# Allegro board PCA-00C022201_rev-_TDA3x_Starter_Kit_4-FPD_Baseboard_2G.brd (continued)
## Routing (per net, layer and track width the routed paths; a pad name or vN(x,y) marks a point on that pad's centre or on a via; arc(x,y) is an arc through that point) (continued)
VDDIO_960: length 9.2
  TOP w0.381: v1(30.82,39.5) 31.05,39.28 C123.1
  TOP w0.508: C58.1 C59.1 39.89,30.92 L10.2 ; C58.1 39.72,29.97 38.72,29.97 38.55,29.8 v1(37.92,29.8) ; C58.1 C60.2
  BOTTOM w0.292: v1(37.92,29.8) U6.16
  BOTTOM w0.381: v1(33.66,37.08) R59.1 ; U7.4 v1(30.82,39.5) ; R42.1 v1(32.96,35.94)
VDDIO_HDMI_IN: length 15.5
  TOP w0.305: U44.23 48.78,43.93 v1(48.51,44.2) ; v1(69.6,61.02) 69.94,60.68 U45.8 71.47,59.46 v1(71.68,59.24) ; U44.44 v1(57.25,36.32) ; U44.34 v1(52.25,36.32)
  TOP w0.381: R283.1 v1(66.23,48.77) ; R278.2 v1(63.44,55.05) ; R286.2 v1(62.73,52.07)
  BOTTOM w0.381: R282.1 62.68,55.05 v1(63.44,55.05) ; R283.1 v1(66.23,48.77) ; v1(57.25,36.32) 57.25,37.05 C230.1 ; R287.2 v1(62.67,39.94) ; R280.1 v1(49.53,52.83) ; v1(48.51,44.2) 49.27,44.2 C232.1 ; v1(71.68,59.24) C264.1 ; R305.1 v1(69.6,61.02)
  vias: v1(50.29,37.27) v1(51.31,36.32)
VDDIO_PHY: length 5.9
  TOP w0.203: v1(89.79,28.83) 90.05,29.09 U9.41 ; U9.19 90.55,36.83 v1(90.55,37.72) ; v1(86.36,33.78) 86.52,33.63 U9.30
  TOP w0.381: R121.1 v1(88.9,25.34) ; v1(90.55,37.72) 90.42,37.85 R311.1 90.42,39.11 v1(90.42,39.12) 90.42,39.75 R125.1
  vias: v1(88.9,28.83)
VDDL: length 16
  TOP w0.508: C32.1 32.84,23.58 33.96,24.7 33.96,26.73 33.26,27.43 33.26,29.38 33.68,29.8 C31.1 C34.2 35.9,29.83 v1(35.9,30.61) ; v1(31.9,20.09) 32.26,20.45 32.65,20.45 L5.2 32.84,20.64 C33.2
  TOP w0.635: C33.2 C32.1
  BOTTOM w0.292: U6.13 v1(35.9,30.61) ; U6.44 v1(31.9,20.09)
VIN1A_CLK0: length 45.4
  TOP w0.127: J14.73 57.02,14.73 57.15,14.86 57.15,31.56 v1(56.71,32) ; R271.1 TP84.1
  BOTTOM w0.127: TP84.1 44.32,41.15 44.32,35.43 46.74,33.02 53.31,31.88 53.85,31.88 v1(56.71,32)
VIN1A_D0: length 34.3
  TOP w0.127: J14.74 v1(57.02,4.83) ; RN1.4 v1(56.68,32.89)
  INNER2 w0.127: v1(57.02,4.83) 57.02,14.1 52.13,18.99 52.13,28.35 v1(56.68,32.89)
VIN1A_D1: length 34.6
  TOP w0.127: J14.71 56.52,14.73 56.13,15.12 56.13,15.48 56.26,15.61 56.52,15.61 56.64,15.74 56.64,15.99 56.52,16.12 56.26,16.12 56.13,16.24 56.13,16.5 56.26,16.62 56.52,16.62 56.64,16.75 56.64,17.01 56.52,17.13 56.26,17.13 56.13,17.26 56.13,17.51 56.26,17.64 56.52,17.64 56.64,17.77 56.64,18.02 56.52,18.15 56.26,18.15 56.13,18.28 56.13,18.53 56.26,18.66 56.52,18.66 56.64,18.78 56.64,19.04 56.52,19.16 56.26,19.16 56.13,19.29 56.13,19.55 56.26,19.67 56.52,19.67 56.64,19.8 56.64,20.05 56.52,20.18 56.26,20.18 56.13,20.31 56.13,20.56 56.26,20.69 56.52,20.69 56.64,20.82 56.64,21.07 56.52,21.2 56.26,21.2 56.13,21.32 56.13,22.45 56.26,22.58 56.52,22.58 56.64,22.71 56.64,22.96 56.52,23.09 56.26,23.09 56.13,23.21 56.13,23.47 56.26,23.59 56.52,23.59 56.64,23.72 56.64,23.98 56.52,24.1 56.26,24.1 56.13,24.23 56.13,25.62 56.26,25.75 56.52,25.75 56.64,25.87 56.64,26.13 56.52,26.26 56.26,26.26 56.13,26.38 56.13,26.64 56.26,26.76 56.52,26.76 56.64,26.89 56.64,27.14 56.52,27.27 56.26,27.27 56.13,27.4 56.13,27.65 56.26,27.78 56.52,27.78 56.64,27.91 56.64,28.16 56.52,28.29 56.26,28.29 56.13,28.41 56.13,28.67 56.26,28.8 56.52,28.8 56.64,28.92 56.64,29.18 56.52,29.3 56.26,29.3 56.13,29.43 56.13,29.68 56.26,29.81 56.52,29.81 56.64,29.94 56.64,30.19 56.52,30.32 56.26,30.32 56.13,30.45 56.13,30.7 56.26,30.83 56.52,30.83 56.64,30.95 56.64,31.21 56.52,31.34 56.26,31.34 56.13,31.46 RN1.3
VIN1A_D2: length 34.2
  TOP w0.127: RN1.2 55.63,32.52 55.12,32 55.12,31.46 55.24,31.34 55.5,31.34 55.63,31.21 55.63,30.95 55.5,30.83 55.24,30.83 55.12,30.7 55.12,30.45 55.24,30.32 55.5,30.32 55.63,30.19 55.63,29.94 55.5,29.81 55.24,29.81 55.12,29.68 55.12,29.43 55.24,29.3 55.5,29.3 55.63,29.18 55.63,28.92 55.5,28.8 55.24,28.8 55.12,28.67 55.12,28.41 55.24,28.29 55.5,28.29 55.63,28.16 55.63,27.91 55.5,27.78 55.24,27.78 55.12,27.65 55.12,27.4 55.24,27.27 55.5,27.27 55.63,27.14 55.63,26.89 55.5,26.76 55.24,26.76 55.12,26.64 55.12,26.38 55.24,26.26 55.5,26.26 55.63,26.13 55.63,25.87 55.5,25.75 55.24,25.75 55.12,25.62 55.12,24.21 55.24,24.08 55.5,24.08 55.63,23.96 55.63,23.7 55.5,23.58 55.24,23.58 55.12,23.45 55.12,23.19 55.24,23.07 55.5,23.07 55.63,22.94 55.63,22.69 55.5,22.56 55.24,22.56 55.12,22.43 55.12,21.32 55.24,21.2 55.5,21.2 55.63,21.07 55.63,20.81 55.5,20.69 55.24,20.69 55.12,20.56 55.12,20.31 55.24,20.18 55.5,20.18 55.63,20.05 55.63,19.8 55.5,19.67 55.24,19.67 55.12,19.54 55.12,19.29 55.24,19.16 55.5,19.16 55.63,19.04 55.63,18.78 55.5,18.66 55.24,18.66 55.12,18.53 55.12,18.27 55.24,18.15 55.5,18.15 55.63,18.02 55.63,17.77 55.5,17.64 55.24,17.64 55.12,17.51 55.12,17.26 55.24,17.13 55.5,17.13 55.63,17 55.63,16.75 55.5,16.62 55.24,16.62 55.12,16.5 55.12,15.37 56.02,14.47 J14.69
VIN1A_D3: length 34.4
  TOP w0.127: RN1.1 v1(55.08,32.89) ; J14.72 v1(56.52,5.59)
  INNER2 w0.127: v1(55.08,32.89) 55.08,32.22 51.05,28.19 51.05,19.3 56.52,13.84 v1(56.52,5.59)
VIN1A_D4: length 34.7
  TOP w0.127: J14.70 v1(56.02,4.83) ; RN2.4 v1(54.14,32.89)
  INNER2 w0.127: v1(54.14,32.89) 54.14,32.17 49.91,27.94 49.91,19.68 56.02,13.58 v1(56.02,4.83)
VIN1A_D5: length 34.6
  TOP w0.127: J14.68 v1(55.52,5.59) ; RN2.3 v1(53.59,32.45)
  INNER2 w0.127: v1(53.59,32.45) 49.47,28.33 49.47,19.37 55.52,13.32 v1(55.52,5.59)
VIN1A_D6: length 40
  TOP w0.127: J14.67 55.52,14.21 54.17,15.56 54.17,16.46 54.29,16.59 54.48,16.59 54.61,16.71 54.61,16.97 54.48,17.09 53.91,17.09 53.78,17.22 53.78,17.47 53.91,17.6 54.48,17.6 54.61,17.73 54.61,17.98 54.48,18.11 53.91,18.11 53.78,18.24 53.78,18.49 53.91,18.62 54.48,18.62 54.61,18.74 54.61,19 54.48,19.13 53.91,19.13 53.78,19.25 53.78,19.51 53.91,19.63 54.48,19.63 54.61,19.76 54.61,20.01 54.48,20.14 53.91,20.14 53.78,20.27 53.78,20.52 53.91,20.65 54.48,20.65 54.61,20.78 54.61,21.03 54.48,21.16 54.29,21.16 54.17,21.28 54.17,22.42 54.29,22.55 54.48,22.55 54.61,22.67 54.61,22.93 54.48,23.05 53.91,23.05 53.78,23.18 53.78,23.44 53.91,23.56 54.48,23.56 54.61,23.69 54.61,23.94 54.48,24.07 54.29,24.07 54.17,24.2 54.17,25.59 54.29,25.71 54.48,25.71 54.61,25.84 54.61,26.09 54.48,26.22 53.91,26.22 53.78,26.35 53.78,26.6 53.91,26.73 54.48,26.73 54.61,26.86 54.61,27.11 54.48,27.24 53.91,27.24 53.78,27.36 53.78,27.62 53.91,27.74 54.48,27.74 54.61,27.87 54.61,28.13 54.48,28.25 53.91,28.25 53.78,28.38 53.78,28.63 53.91,28.76 54.48,28.76 54.61,28.89 54.61,29.14 54.48,29.27 53.91,29.27 53.78,29.4 53.78,29.65 53.91,29.78 54.48,29.78 54.61,29.9 54.61,30.16 54.48,30.28 54.29,30.28 54.17,30.41 54.17,30.92 54.01,31.08 54.01,31.26 54.21,31.46 54.21,31.64 54.03,31.82 53.85,31.82 53.65,31.62 53.47,31.62 53.09,32 RN2.2
VIN1A_D7: length 35
  TOP w0.127: J14.65 55.02,13.94 53.21,15.75 53.21,16.97 53.09,17.09 52.7,17.09 52.58,17.22 52.58,17.48 52.7,17.6 53.09,17.6 53.21,17.73 53.21,17.98 53.09,18.11 52.7,18.11 52.58,18.24 52.58,18.49 52.7,18.62 53.09,18.62 53.21,18.75 53.21,19 53.09,19.13 52.7,19.13 52.58,19.25 52.58,19.51 52.7,19.63 53.09,19.63 53.21,19.76 53.21,20.02 53.09,20.14 52.7,20.14 52.58,20.27 52.58,20.52 52.7,20.65 53.09,20.65 53.21,20.78 53.21,22.69 53.09,22.81 52.7,22.81 52.58,22.94 52.58,23.2 52.7,23.32 53.09,23.32 53.21,23.45 53.21,23.7 53.09,23.83 52.7,23.83 52.58,23.96 52.58,24.21 52.7,24.34 53.09,24.34 53.21,24.47 53.21,26.1 53.09,26.23 52.7,26.23 52.58,26.35 52.58,26.61 52.7,26.73 53.09,26.73 53.21,26.86 53.21,27.11 53.09,27.24 52.7,27.24 52.58,27.37 52.58,27.62 52.7,27.75 53.09,27.75 53.21,27.88 53.21,28.13 53.09,28.26 52.7,28.26 52.58,28.38 52.58,28.64 52.7,28.77 53.09,28.77 53.21,28.89 53.21,29.15 53.09,29.27 52.7,29.27 52.58,29.4 52.58,29.65 52.7,29.78 53.09,29.78 53.21,29.91 53.21,31.11 52.54,31.79 RN2.1
VIN1A_D8: length 38.2
  TOP w0.127: RN3.4 v1(46.52,37.72) ; J14.66 v1(55.02,4.83)
  INNER2 w0.127: v1(55.02,4.83) 55.02,13.06 49.02,19.05 49.02,33.15 46.52,35.65 v1(46.52,37.72)
VIN1A_D9: length 33.2
  TOP w0.127: J14.63 54.52,13.68 52.07,16.13 52.07,29.59 45.85,35.81 45.85,38.61 46.11,38.87 RN3.3
VIN1A_D10: length 34
  TOP w0.127: RN3.2 45.84,39.37 45.34,38.86 45.34,35.56 51.05,29.84 51.05,16.38 54.02,13.42 J14.61
VIN1A_D11: length 39.5
  TOP w0.127: RN3.1 45.63,39.92 44.83,39.12 44.83,35.31 49.78,30.35 49.78,16.89 53.34,13.34 53.34,10.54 52.32,9.53 49.53,9.53 49.24,9.82 J14.59
VIN1A_D12: length 41.7
  TOP w0.127: RN4.4 45.81,40.86 44.32,39.37 44.32,35.05 49.28,30.1 49.28,16.64 52.96,12.95 52.96,10.79 52.07,9.91 49.91,9.91 48.9,10.92 48.26,10.92 48.01,10.68 J14.57
VIN1A_D13: length 42.6
  TOP w0.127: RN4.3 45.41,41.41 v1(45.15,41.15) ; J14.62 v1(54.02,4.83)
  INNER2 w0.127: v1(45.15,41.15) 45.15,35.5 48.13,32.51 48.13,18.41 54.02,12.53 v1(54.02,4.83)
VIN1A_D14: length 42.6
  TOP w0.127: J14.64 v1(54.52,5.59) ; RN4.2 v1(45.78,41.91)
  INNER2 w0.127: v1(45.78,41.91) 45.78,35.62 48.58,32.83 48.58,18.73 54.52,12.79 v1(54.52,5.59)
VIN1A_D15: length 43.8
  TOP w0.127: RN4.1 45.5,42.46 43.81,40.77 43.81,34.8 48.77,29.84 48.77,16.38 52.58,12.57 52.58,11.05 51.82,10.29 50.29,10.29 49.21,11.37 48.07,11.37 47.51,10.81 J14.55
VIN1A_DE0: length 34.7
  TOP w0.127: J14.75 57.52,14.46 58.17,15.11 58.17,22.46 58.29,22.59 58.8,22.59 58.93,22.72 58.93,22.97 58.8,23.1 58.29,23.1 58.17,23.22 58.17,23.48 58.29,23.61 58.8,23.61 58.93,23.73 58.93,23.99 58.8,24.11 58.29,24.11 58.17,24.24 58.17,25.7 58.29,25.82 58.8,25.82 58.93,25.95 58.93,26.2 58.8,26.33 58.29,26.33 58.17,26.46 58.17,26.71 58.29,26.84 58.8,26.84 58.93,26.97 58.93,27.22 58.8,27.35 58.29,27.35 58.17,27.47 58.17,27.73 58.29,27.86 58.8,27.86 58.93,27.98 58.93,28.24 58.8,28.36 58.29,28.36 58.17,28.49 58.17,28.74 58.29,28.87 58.8,28.87 58.93,29 58.93,29.25 58.8,29.38 58.29,29.38 58.17,29.51 58.17,29.76 58.29,29.89 58.8,29.89 58.93,30.01 58.93,30.27 58.8,30.4 58.29,30.4 58.17,30.52 58.17,30.78 58.29,30.9 58.8,30.9 58.93,31.03 58.93,31.28 58.8,31.41 58.29,31.41 58.17,31.54 58.17,32.19 TP86.1 57.78,33.08 R274.1
VIN1A_HSYNC0: length 34
  TOP w0.127: J14.78 v1(58.02,4.83) ; TP85.1 R272.1
  INNER2 w0.127: v1(58.02,4.83) 58.02,14.63 54.17,18.48 54.17,27.5 58.93,32.26 TP85.1
VIN1A_VSYNC0: length 37.3
  TOP w0.127: J14.76 v1(57.52,5.59) ; TP87.1 60.07,33.08 R273.1
  INNER2 w0.127: TP87.1 59.63,33.53 58.61,33.53 58.23,33.15 58.23,32.32 53.15,27.24 53.15,18.73 57.52,14.37 v1(57.52,5.59)
ADC_IN2: length 77.7
  TOP w0.152: J14.20 v1(38.51,5.59)
  TOP w0.381: D21.C v1(24.19,57.59)
  INNER1 w0.152: v1(24.19,57.59) 28.64,57.59 30.35,55.88 33.15,55.88 36.7,52.32 36.7,47.62 38.61,45.72 38.61,44.07 37.97,43.43 37.97,34.54 41.02,31.5 41.02,28.45 41.91,27.56 41.91,26.92 34.29,19.3 34.29,13.46 36.32,11.43 36.32,9.78 37.4,8.7 37.4,7.94 38.51,6.83 v1(38.51,5.59)
  BOTTOM w0.254: v1(24.19,57.59) 22.61,57.59 22.29,57.91 R231.1 R26.1
ADC_IN4: length 70.3
  TOP w0.152: v1(37.97,8.38) 37.51,8.84 J14.15 ; v1(33.27,62.1) 28.7,62.1 28.26,62.55 R251.2
  INNER1 w0.152: v1(37.97,8.38) 37.97,10.79 37.53,11.24 37.53,11.75 37.34,11.94 37.34,12.83 37.97,13.46 37.97,18.41 39.37,19.81 39.37,22.61 43.81,27.05 43.81,30.73 39.24,35.31 39.24,42.93 39.88,43.56 39.88,46.35 38.48,47.75 38.48,56.9 v1(33.27,62.1)
ADC_IN5: length 89.5
  TOP w0.152: v1(37.01,10.92) J14.13
  TOP w0.254: R252.2 v1(6.67,60.26)
  INNER1 w0.152: v1(37.01,10.92) 37.01,11.5 36.7,11.81 36.7,18.03 38.73,20.07 38.73,22.86 42.55,26.67 42.55,30.99 38.61,34.92 38.61,43.18 39.24,43.81 39.24,46.1 37.97,47.37 37.97,56.64 32.99,61.63 23.02,61.63 22.23,60.83 16.89,60.83 15.24,62.48 15.24,63.12 14.22,64.14 11.68,64.14 7.81,60.26 v1(6.67,60.26)
ADV7611_RSTN: length 83.9
  TOP w0.127: v1(63.75,42.67) 63.5,42.93 U44.56 ; U22.10 27.06,8.63 24.89,10.79 24.89,13.08 18.8,19.18 18.8,34.67 24.19,40.07 32.51,40.07 32.96,39.62 42.8,39.62 43.18,39.24 v1(43.18,38.61)
  INNER1 w0.127: v1(43.18,38.61) 43.69,38.61 46.35,41.27 51.69,41.27 52.07,41.66 57.02,41.66 58.29,42.93 61.09,42.93 61.34,42.67 v1(63.75,42.67)
  BOTTOM w0.127: v1(63.75,42.67) 63.75,41.91 R290.1
ADV7611_SCL: length 26.7
  TOP w0.127: v1(63.31,41.02) 62.9,41.43 U44.53 ; v1(42.99,36.39) R291.2 R288.1
  INNER1 w0.127: v1(42.99,36.39) 46.1,39.5 59.82,39.5 61.75,41.43 62.9,41.43 v1(63.31,41.02)
ADV7611_SDA: length 24.4
  TOP w0.127: R289.1 R292.2 v1(42.99,37.53) ; v1(62.48,41.93) U44.54
  INNER1 w0.127: v1(42.99,37.53) 43.37,37.53 46.42,40.58 57.85,40.58 59.2,41.93 v1(62.48,41.93)
BB_3V3_PG: length 47
  TOP w0.152: TP56.1 76.02,2.62 J14.130
  TOP w0.254: U1.10 106.95,15.93 v1(106.95,15.56)
  INNER2 w0.152: TP28.1 99.69,17.14 97.03,14.48 97.03,9.02 v1(91.06,3.05)
  BOTTOM w0.152: TP56.1 77.3,1.33 86.8,1.33 88.52,3.05 v1(91.06,3.05)
  BOTTOM w0.203: v1(106.95,15.56) 103.71,18.8 TP28.1 98.43,18.8 R8.2
BOARD_ID0: length 13.1
  TOP w0.127: R185.2 R186.1 11.49,9.08 12.83,10.41 20.7,10.41 21.19,9.93 U22.13
BOARD_ID1: length 10.3
  TOP w0.127: U22.14 21.08,9.28 20.45,9.91 14.99,9.91 14.16,9.08 R187.1 R188.2
BOARD_ID2: length 7.5
  TOP w0.127: R190.2 R189.1 16.83,9.08 17.14,9.4 20.19,9.4 20.97,8.63 U22.15
BOARD_ID3: length 4.2
  TOP w0.127: U22.16 20.85,7.98 20.19,8.64 R191.1 R192.2
BUF_INPUT0: length 1.1
  BOTTOM w0.152: R265.1 J28.2
BUF_INPUT1: length 1.1
  BOTTOM w0.152: R266.1 J28.4
BUF_OUT0: length 1.1
  BOTTOM w0.152: R267.1 J28.6
BUF_OUT1: length 1.1
  BOTTOM w0.152: R268.1 J28.8
CSI2_0_DX0: length 47.8
  TOP w0.127: v1(65.18,5.36) 65.03,5.51 64.57,5.51 64.44,5.38 64.44,3.72 J14.104
  BOTTOM w0.127: v1(65.18,5.36) 65.03,5.51 64.53,5.51 64.1,5.94 64.1,7.39 65.71,9 65.71,9.11 65.65,9.17 65.65,9.28 65.72,9.35 65.82,9.35 65.89,9.29 66,9.29 66.07,9.36 66.07,9.47 66.01,9.52 66.01,9.63 66.09,9.7 66.19,9.7 66.25,9.64 66.35,9.64 67.18,10.47 67.18,13.72 62.46,18.44 50.4,18.44 42.67,26.17 38.18,26.17 U6.23
CSI2_0_DX1: length 47.8
  TOP w0.127: J14.109 65.94,9.89 65.94,11.67 65.61,12 65.23,12 v1(65.08,12.15)
  BOTTOM w0.127: v1(65.08,12.15) 65.23,12 65.62,12 65.86,12.24 65.86,13.07 63.13,15.8 63.03,15.8 62.97,15.74 62.87,15.74 62.79,15.82 62.79,15.92 62.85,15.98 62.85,16.08 62.77,16.16 62.67,16.16 62.6,16.09 62.5,16.09 62.42,16.17 62.42,16.27 62.49,16.34 62.49,16.44 62.2,16.73 61.43,16.73 61.18,16.48 61.18,15.96 60.84,15.62 60.17,15.62 59.83,15.96 59.83,16.79 59.7,16.92 59.32,16.92 59.2,16.79 59.2,15.96 58.86,15.62 58.18,15.62 57.85,15.96 57.85,16.79 57.72,16.92 57.34,16.92 57.21,16.79 57.21,15.96 56.88,15.62 56.2,15.62 55.86,15.96 55.86,16.79 55.74,16.92 55.35,16.92 55.23,16.79 55.23,15.96 54.89,15.62 54.21,15.62 53.88,15.96 53.88,16.79 53.75,16.92 53.37,16.92 53.24,16.79 53.24,15.96 52.91,15.62 52.23,15.62 51.89,15.96 51.89,16.5 51.5,16.89 50.04,16.89 41.76,25.17 38.18,25.17 U6.25
CSI2_0_DX2: length 47.8
  TOP w0.127: v1(63.51,12.15) 63.67,12 64.11,12 64.44,11.67 64.44,9.89 J14.103
  BOTTOM w0.127: v1(63.51,12.15) 63.67,12 63.95,12 64.11,12.16 64.11,13.03 63.1,14.05 62.35,14.05 62.28,13.97 62.28,13.74 62.2,13.67 62.1,13.67 62.03,13.74 62.03,13.97 61.95,14.05 61.26,14.05 61.14,13.92 61.14,12.13 60.8,11.8 60.12,11.8 59.79,12.13 59.79,13.92 59.66,14.05 59.28,14.05 59.15,13.92 59.15,12.11 58.82,11.77 58.14,11.77 57.8,12.11 57.8,13.92 57.68,14.05 57.3,14.05 57.17,13.92 57.17,12.11 56.83,11.77 56.16,11.77 55.82,12.11 55.82,13.92 55.49,14.25 50.77,14.25 40.85,24.17 38.18,24.17 U6.27
CSI2_0_DX3: length 47.8
  TOP w0.127: J14.98 62.94,3.72 62.94,5.38 63.07,5.51 63.32,5.51 v1(63.47,5.36)
  BOTTOM w0.127: v1(63.47,5.36) 63.32,5.51 62.95,5.51 62.57,5.88 62.57,9.12 61.76,9.93 61.19,9.93 61.11,9.86 61.11,9.77 61.04,9.7 60.93,9.7 60.86,9.77 60.86,9.86 60.78,9.93 60.68,9.93 60.6,9.86 60.6,9.77 60.53,9.7 60.42,9.7 60.35,9.77 60.35,9.86 60.27,9.93 59.78,9.93 59.54,9.69 59.54,9.35 59.2,9.02 58.53,9.02 58.19,9.35 58.19,9.8 58.06,9.93 57.68,9.93 57.56,9.8 57.56,9.35 57.22,9.02 56.54,9.02 56.21,9.35 56.21,9.71 55.99,9.93 55.22,9.93 52.33,12.83 50.04,12.83 49.52,13.35 49.34,13.35 48.58,12.6 48.11,12.6 47.63,13.08 47.63,13.55 48.38,14.31 48.38,14.49 48.11,14.76 47.93,14.76 47.18,14 46.7,14 46.23,14.48 46.23,14.96 46.98,15.71 46.98,15.89 46.71,16.16 46.53,16.16 45.78,15.41 45.3,15.41 44.82,15.88 44.82,16.36 45.58,17.11 45.58,17.55 39.95,23.17 38.18,23.17 U6.29
CSI2_0_DX4: length 47.8
  TOP w0.127: J14.97 62.94,9.75 62.94,7.9 62.61,7.57 62.18,7.57 v1(62.03,7.42)
  BOTTOM w0.127: v1(62.03,7.42) 61.88,7.57 54.41,7.57 52.45,9.53 50.42,9.53 50.16,9.78 49.02,9.78 48.68,10.11 48.68,10.85 48.55,10.97 48.17,10.97 48.04,10.85 48.04,10.11 47.71,9.78 45.09,9.78 43.89,10.98 43.89,11.45 45.21,12.78 45.21,12.96 44.94,13.23 44.76,13.23 43.44,11.9 42.97,11.9 41.81,13.06 41.81,14.41 42.14,14.75 43.2,14.75 43.33,14.88 43.33,15.26 43.2,15.38 42.14,15.38 41.81,15.72 41.81,16.4 42.14,16.73 43.2,16.73 43.33,16.86 43.33,17.24 43.2,17.37 42.14,17.37 41.81,17.7 41.81,19.38 39.02,22.17 38.18,22.17 U6.31
CSI2_0_DY0: length 47.9
  TOP w0.127: J14.102 64.09,3.72 64.09,5.53 64.42,5.87 64.8,5.87 65.03,5.87 v1(65.18,6.02)
  BOTTOM w0.127: v1(65.18,6.02) 65.03,5.87 64.68,5.87 64.45,6.09 64.45,7.24 67.54,10.33 67.54,13.87 62.61,18.8 50.55,18.8 42.82,26.53 38.18,26.53 U6.22
CSI2_0_DY1: length 47.8
  TOP w0.127: J14.107 65.59,9.89 65.59,11.52 65.46,11.65 65.23,11.65 v1(65.08,11.49)
  BOTTOM w0.127: v1(65.08,11.49) 65.23,11.65 65.77,11.65 66.22,12.1 66.22,13.22 62.35,17.08 61.28,17.08 60.82,16.63 60.82,16.1 60.7,15.98 60.32,15.98 60.19,16.1 60.19,16.94 59.85,17.27 59.18,17.27 58.84,16.94 58.84,16.1 58.71,15.98 58.33,15.98 58.2,16.1 58.2,16.94 57.87,17.27 57.19,17.27 56.86,16.94 56.86,16.1 56.73,15.98 56.35,15.98 56.22,16.1 56.22,16.94 55.88,17.27 55.21,17.27 54.87,16.94 54.87,16.1 54.74,15.98 54.36,15.98 54.24,16.1 54.24,16.94 53.9,17.27 53.22,17.27 52.89,16.94 52.89,16.1 52.76,15.98 52.38,15.98 52.25,16.1 52.25,16.65 51.65,17.25 50.19,17.25 41.91,25.53 38.18,25.53 U6.24
CSI2_0_DY2: length 47.8
  TOP w0.127: J14.101 64.09,9.89 64.09,11.52 63.96,11.65 63.66,11.65 v1(63.51,11.49)
  BOTTOM w0.127: v1(63.51,11.49) 63.66,11.65 64.1,11.65 64.47,12.01 64.47,13.18 63.25,14.4 61.12,14.4 60.78,14.07 60.78,12.28 60.65,12.15 60.27,12.15 60.14,12.28 60.14,14.07 59.81,14.4 59.13,14.4 58.8,14.07 58.8,12.26 58.67,12.13 58.29,12.13 58.16,12.26 58.16,14.07 57.83,14.4 57.15,14.4 56.81,14.07 56.81,12.26 56.69,12.13 56.3,12.13 56.18,12.26 56.18,14.07 55.64,14.61 50.92,14.61 41,24.53 38.18,24.53 U6.26
CSI2_0_DY3: length 47.8
  TOP w0.127: J14.96 62.59,3.72 62.59,5.53 62.92,5.87 63.32,5.87 v1(63.47,6.02)
  BOTTOM w0.127: v1(63.47,6.02) 63.32,5.87 63.09,5.87 62.93,6.03 62.93,9.27 61.91,10.29 59.63,10.29 59.18,9.84 59.18,9.5 59.06,9.37 58.67,9.37 58.55,9.5 58.55,9.95 58.21,10.29 57.53,10.29 57.2,9.95 57.2,9.5 57.07,9.37 56.69,9.37 56.56,9.5 56.56,9.86 56.13,10.29 55.37,10.29 52.48,13.18 50.19,13.18 49.67,13.71 49.19,13.71 48.44,12.95 48.26,12.95 47.99,13.22 47.99,13.4 48.74,14.16 48.74,14.63 48.26,15.11 47.79,15.11 47.03,14.36 46.85,14.36 46.58,14.63 46.58,14.81 47.34,15.56 47.34,16.04 46.86,16.52 46.38,16.52 45.63,15.76 45.45,15.76 45.18,16.03 45.18,16.21 45.93,16.97 45.93,17.69 40.1,23.53 38.18,23.53 U6.28
CSI2_0_DY4: length 47.8
  TOP w0.127: J14.95 62.59,9.75 62.59,8.05 62.46,7.93 62.18,7.93 v1(62.03,8.08)
  BOTTOM w0.127: U6.30 38.18,22.53 39.16,22.53 42.16,19.53 42.16,17.85 42.29,17.72 43.35,17.72 43.69,17.39 43.69,16.71 43.35,16.38 42.29,16.38 42.16,16.25 42.16,15.87 42.29,15.74 43.35,15.74 43.69,15.4 43.69,14.73 43.35,14.39 42.29,14.39 42.16,14.27 42.16,13.21 43.11,12.26 43.29,12.26 44.62,13.58 45.09,13.58 45.57,13.1 45.57,12.63 44.25,11.31 44.25,11.13 45.24,10.13 47.56,10.13 47.69,10.26 47.69,10.99 48.02,11.33 48.7,11.33 49.04,10.99 49.04,10.26 49.16,10.13 50.31,10.13 50.57,9.88 52.6,9.88 54.55,7.93 60.25,7.93 60.33,8 60.33,8.09 60.4,8.17 60.51,8.17 60.58,8.09 60.58,8 60.65,7.93 60.76,7.93 60.83,8 60.83,8.08 60.91,8.15 61.01,8.15 61.09,8.08 61.09,8 61.16,7.93 61.88,7.93 v1(62.03,8.08)
CVDD_HDMI_IN: length 4.2
  TOP w0.305: v1(52.58,50.1) 52.75,49.93 U44.14 ; U44.2 v1(58.75,50.04)
  BOTTOM w0.457: C246.1 52.32,49.85 v1(52.58,50.1) ; v1(58.75,50.04) 58.93,49.86 C247.1
  vias: v1(49.53,49.78) v1(49.53,49.02) v1(60.45,48.51)
DCAN1_H: length 12.6
  TOP w0.127: J28.1 112.27,66.29 112.07,66.49 D9.1 108.33,66.49 107.64,67.18 106.24,67.18 105.44,66.38 R92.1 105.43,66.36 C107.1 103.63,66.36 103.5,66.23 U10.7
DCAN1_L: length 12.6
  TOP w0.127: J28.3 112.39,65.02 112.07,64.7 D8.2 108.26,64.7 107.57,64.01 106.24,64.01 105.44,64.81 R93.1 105.43,64.84 C108.1 103.63,64.84 103.5,64.96 U10.6
DCAN1_RX: length 76.3
  TOP w0.152: J14.113 v1(67.02,8.64) ; v1(99.82,62.67) 99,61.85 88.39,61.85 86.87,60.33 86.87,58.8 85.22,57.15 84.33,57.15 77.47,50.29 v1(77.47,31.75)
  INNER1 w0.152: v1(77.47,31.75) 77.47,22.73 72.14,17.4 72.14,13.76 v1(67.02,8.64)
  BOTTOM w0.152: v1(99.82,62.67) R91.1
DCAN1_STSB: length 119.5
  TOP w0.152: U22.11 v1(30.1,9.28) ; v1(75.69,29.97) 75.69,49.4 84.07,57.78 85.09,57.78 86.36,59.05 86.36,60.58 88.07,62.29 98.49,62.29 v1(100.52,64.33)
  INNER1 w0.152: v1(30.1,9.28) 30.86,8.51 30.86,7.62 34.68,3.81 47.94,3.81 49.72,5.59 51.18,5.59 53.34,7.75 56.26,7.75 62.87,14.35 67.06,14.35 75.69,22.99 v1(75.69,29.97)
  BOTTOM w0.152: v1(100.52,64.33) 102.17,65.98 R89.1
DCAN1_TX: length 75.6
  TOP w0.152: v1(78.11,32.38) 78.11,49.97 v1(83.19,55.05) ; J14.115 67.52,8.31 v1(67.03,7.82)
  INNER1 w0.152: v1(67.03,7.82) 72.64,13.44 72.64,17.27 78.11,22.73 v1(78.11,32.38)
  BOTTOM w0.152: R90.1 97.41,65.53 92.58,60.71 88.84,60.71 v1(83.19,55.05)
DCAN2_RX: length 67.3
  TOP w0.152: J14.110 v1(66.02,4.83)
  INNER2 w0.152: J27.14 41.15,50.67 41.15,46.99 44.51,43.62 44.51,34.8 46.04,33.27 46.04,19.75 53.47,12.32 53.47,4.45 53.85,4.06 65.25,4.06 v1(66.02,4.83)
DCAN2_TX: length 71.2
  TOP w0.152: J14.108 v1(65.52,2.54)
  INNER2 w0.152: v1(65.52,2.54) 64.5,3.56 53.59,3.56 52.96,4.19 52.96,12.06 45.59,19.43 45.59,33.02 43.94,34.67 43.94,43.18 38.48,48.64 38.48,53.09 J27.12
EDID_EEPROM_WP: length 112.5
  TOP w0.152: v1(70.05,57.76) 69.29,58.53 U45.7 ; SW2.4 v1(15.24,5.71)
  INNER1 w0.152: v1(37.08,46.16) 36.13,45.21 32.13,45.21 26.54,39.62 26.54,32.51 22.48,28.45 22.48,22.35 20.32,20.19 20.32,19.3 19.3,18.29 19.3,9.65 21.72,7.24 21.72,2.6 21.34,2.22 18.22,2.22 16.07,4.38 16.07,4.89 v1(15.24,5.71)
  BOTTOM w0.152: v1(37.08,46.16) 38.35,47.43 38.35,57.78 38.86,58.29 43.43,58.29 45.72,60.58 60.58,60.58 61.91,59.24 R305.2 69.6,58.22 v1(70.05,57.76)
EDID_SCL: length 7.8
  TOP w0.127: TP88.1 68.64,57.88 U45.6
  BOTTOM w0.127: U46.4 66.1,54.03 68.33,56.26 68.33,56.97 TP88.1
EDID_SDA: length 5.5
  TOP w0.127: U45.5 67.99,57.9 TP89.1
  BOTTOM w0.127: TP89.1 67.06,56.97 67.06,56.64 66.4,55.98 U46.7
EDID_SEL: length 99.7
  TOP w0.152: R307.2 v1(65.05,51.44) ; SW2.3 v1(15.24,4.45)
  INNER1 w0.152: v1(37.97,45.09) 37.47,44.58 32.51,44.58 27.18,39.24 27.18,32.26 24,29.08 24,22.99 20.95,19.94 20.95,19.05 19.94,18.03 19.94,9.91 22.23,7.62 22.23,2.41 21.65,1.84 17.84,1.84 v1(15.24,4.45)
  BOTTOM w0.152: U46.1 v1(65.05,51.44) 61.59,51.44 61.09,51.94 60.45,51.94 58.8,53.59 58.8,53.98 58.29,54.48 45.72,54.48 44.45,53.21 44.45,48.77 40.77,45.09 v1(37.97,45.09)
EMU0: length 52.2
  TOP w0.127: J14.175 v1(87.52,8.47)
  INNER2 w0.127: v1(87.52,8.47) 87.52,8.11 89.41,6.22 89.41,3.43 87.5,1.52 78.17,1.52 75.12,4.57 75.12,5.27 74.17,6.22 74.17,6.99 62.85,18.3 62.85,23.05 v1(60.95,24.96)
  BOTTOM w0.127: J13.19 59.89,24.66 60.19,24.96 v1(60.95,24.96)
EMU1: length 55.5
  TOP w0.127: v1(89.2,7.94) 87.3,7.94 87.02,8.22 J14.173
  INNER2 w0.127: v1(61.58,20.19) 62.09,19.68 62.09,17.54 73.15,6.48 73.15,4.06 74.87,2.35 74.87,1.52 75.63,0.76 88.01,0.76 90.17,2.92 90.17,6.97 v1(89.2,7.94)
  BOTTOM w0.127: J13.21 59.39,22.1 59.18,21.89 59.18,20.45 59.44,20.19 v1(61.58,20.19)
EMU_RSTN: length 38.9
  TOP w0.127: J14.172 v1(86.52,5.52) ; R108.2 63.15,30.87 v1(63.39,30.63)
  INNER2 w0.127: v1(86.52,5.52) 86.36,5.97 65.15,27.18 65.15,28.87 v1(63.39,30.63)
  BOTTOM w0.127: J13.6 v1(63.39,30.63)
ENET_CLKIN: length 2.5
  TOP w0.127: R233.2 93.32,38.33 92.56,37.56 U9.15
FPD_960_EN: length 38.6
  TOP w0.152: U22.17 23.2,7.33 v1(23.75,7.87) ; R270.1 v1(28.7,39.5)
  INNER1 w0.152: v1(28.7,39.5) 27.81,38.61 27.81,32 24.64,28.83 24.64,21.34 20.83,17.53 20.83,13.59 21.46,12.95 21.46,10.16 v1(23.75,7.87)
FPD_960_GPIO4: length 42.1
  TOP w0.152: TP22.1 29.44,4.72 U22.4
  INNER1 w0.152: v1(39.12,29.26) 36.12,29.26 34.16,27.3 34.16,24.97 30.21,21.02 26.29,21.02 23.24,17.97 23.24,13.59 23.88,12.95 23.88,10.29 TP22.1
  BOTTOM w0.152: U6.17 38.65,29.1 38.81,29.26 v1(39.12,29.26)
FPD_960_GPIO5: length 38.3
  TOP w0.152: TP24.1 29.46,5.46 29.38,5.37 U22.5
  INNER1 w0.152: TP24.1 29.46,5.46 24.38,10.54 24.38,13.21 23.8,13.79 23.8,17.83 26.54,20.57 30.53,20.57 36.7,26.75 36.7,27.5 37.81,28.6 v1(38.91,28.6)
  BOTTOM w0.152: U6.18 v1(38.91,28.6)
FPD_960_GPIO6: length 35.7
  TOP w0.152: TP23.1 29.27,6.02 U22.6
  INNER1 w0.152: v1(39.22,27.99) 38.66,27.99 38.23,27.56 38.23,25.27 32.32,19.37 29.15,19.37 24.89,15.11 24.89,10.79 28.83,6.86 TP23.1
  BOTTOM w0.152: v1(39.22,27.99) 39.11,28.1 U6.19
FPD_960_GPIO7: length 32.1
  TOP w0.152: TP25.1 29.34,7.49 29.34,6.99 29.03,6.68 U22.7
  INNER1 w0.152: v1(38.98,27.37) 38.98,25.13 32.7,18.86 29.27,18.86 26.1,15.68 26.1,12.26 TP25.1
  BOTTOM w0.152: v1(38.98,27.37) 38.75,27.6 U6.20
FPD_960_IDX: length 7.1
  BOTTOM w0.152: U6.46 30.9,19.63 32.5,18.04 C63.1 R53.1 R51.2
FPD_960_MODE: length 9
  BOTTOM w0.152: U6.45 31.41,19.83 32.44,18.8 36.88,18.8 37.21,18.47 R58.2 R61.1
FPD_960_PDB: length 9.5
  TOP w0.152: v1(29.65,36.83) 29.65,37.53 R269.1 R270.2
  BOTTOM w0.152: v1(29.65,36.83) 29.65,31.94 30.9,30.69 U6.3
FPD_960_REFCLK: length 1.2
  BOTTOM w0.127: U7.3 R45.1
FPD_960_SCL: length 8.2
  BOTTOM w0.127: R38.1 R39.1 38.73,34.67 38.35,34.29 37.97,34.29 36.7,33.02 36.7,32.26 35.41,30.96 35.41,29.8 U6.12
FPD_960_SCL2: length 15.5
  TOP w0.127: v1(34.67,35.24) R44.1 R328.2
  INNER2 w0.127: J29.1 36.45,37.02 v1(34.67,35.24)
  BOTTOM w0.127: R43.1 R44.1 v1(34.67,35.24) 34.23,34.8 34.23,33.08 33.41,32.26 U6.8
FPD_960_SDA: length 10.8
  BOTTOM w0.127: R37.1 R36.1 38.23,37.53 37.85,37.15 37.85,34.92 36.2,33.27 36.2,32.51 34.9,31.22 34.9,29.8 U6.11
FPD_960_SDA2: length 14.4
  TOP w0.127: v1(34.67,37.21) 34.67,38.03 R329.2
  BOTTOM w0.127: U6.7 32.9,32.52 33.78,33.4 33.78,36.32 v1(34.67,37.21) 34.99,37.53 R40.1 R41.1 35.43,39.88 J29.2
FPD_960_TESTEN: length 18.3
  TOP w0.152: v1(25.4,28.45) SW1.2
  TOP w0.203: v1(31.38,30.58) 32.36,30.58 33.72,31.94 R60.2
  INNER1 w0.152: v1(25.4,28.45) 29.25,28.45 v1(31.38,30.58)
  BOTTOM w0.152: v1(31.38,30.58) 31.39,30.57 31.39,29.81 U6.4
GPIO2_0: length 104
  TOP w0.152: J14.77 58.02,8.87 57.72,8.57 53.21,8.57 52.7,9.08 51.05,9.08 v1(50.48,8.51)
  INNER1 w0.152: v1(24.96,58.29) 24,58.29 18.67,52.96 18.67,9.4 20.19,7.87 20.19,6.67 v1(20.89,5.97)
  BOTTOM w0.152: v1(50.48,8.51) 45.59,8.51 44.45,7.37 39.5,7.37 37.82,5.69 37.82,4.75 37.13,4.06 34.04,4.06 31.94,6.16 23.94,6.16 23.75,5.97 v1(20.89,5.97)
  BOTTOM w0.254: R231.2 22.29,58.93 22.92,58.29 v1(24.96,58.29)
GPIO2_19: length 66.8
  TOP w0.127: R180.1 R234.1 85.41,26.03 TP40.1 ; J14.56 47.51,5.1 v1(48.01,5.59)
  BOTTOM w0.127: TP40.1 85.41,18.67 84.52,17.78 84.52,10.6 86.11,9.02 86.11,8.32 85.53,7.75 85.53,4.38 85.28,4.13 76.14,4.13 74.99,5.27 74.1,5.27 72.77,3.94 53.59,3.94 51.94,5.59 v1(48.01,5.59)
GPIO3_19: length 94.7
  TOP w0.152: U41.6 120.89,60.44 119.89,59.44 116.33,59.44 116.14,59.25 114.11,59.25 113.74,58.88 113.74,58.37 113.41,58.04 111.76,58.04 111.25,58.55 111.25,58.8 110.87,59.18 109.98,59.18 109.09,60.07 92.71,60.07 90.3,57.66 90.3,55.75 80.26,45.72 80.26,31.62 61.02,12.38 J14.89
GPIO3_20: length 98.7
  TOP w0.152: U41.4 120.89,61.74 120.01,62.61 118.11,62.61 116.71,61.21 116.71,60.71 115.7,59.69 113.67,59.69 112.59,60.77 112.59,61.34 112.2,61.72 104.58,61.72 104.08,62.23 100.33,62.23 99.5,61.4 91.76,61.4 88.77,58.42 88.77,56.52 78.74,46.48 78.74,32 59.02,12.28 J14.81
GPIO3_21: length 94.1
  TOP w0.152: J14.85 60.02,12.65 79.25,31.88 79.25,46.23 89.28,56.26 89.28,58.17 92.08,60.96 110.87,60.96 v1(113.16,58.67)
  BOTTOM w0.152: v1(113.16,58.67) R297.1 113.85,59.37 114.24,59.75 119,59.75 119.2,59.55 U42.1
GPIO3_22: length 94.3
  TOP w0.152: J14.87 60.52,12.51 79.76,31.75 79.76,45.97 89.79,56.01 89.79,57.91 92.39,60.52 110.55,60.52 112.01,59.05 v1(112.01,58.67)
  BOTTOM w0.152: R298.1 v1(112.01,58.67) 112.01,58.17 114.17,56.01 116.01,56.01 117.9,57.9 U42.3
GPIO3_23: length 108.4
  TOP w0.152: J14.83 59.52,8.84 58.23,7.56 v1(51.37,7.56)
  INNER1 w0.152: v1(20.89,4.45) 19.94,5.4 18.48,5.4 18.16,5.71 18.16,6.48 17.4,7.24 17.4,46.23 5.84,57.78 v1(5.84,59.44)
  BOTTOM w0.152: v1(51.37,7.56) 50.81,7.05 50.1,6.35 40.96,6.35 37.66,3.05 33.53,3.05 32.38,4.19 31.24,4.19 30.42,3.37 29.78,3.37 28.38,4.76 24.45,4.76 24.13,4.45 v1(20.89,4.45) ; R24.1 6.34,60.82 5.84,60.33 v1(5.84,59.44)
GPIO3_24: length 105.4
  TOP w0.152: J14.79 58.52,8.61 57.98,8.06 52.96,8.06 52.51,8.51 v1(51.37,8.51)
  INNER1 w0.152: v1(23.18,60.77) 20.13,57.72 20.13,56.07 18.03,53.98 18.03,7.43 19.43,6.03 20.07,6.03 v1(20.89,5.21)
  BOTTOM w0.152: v1(20.89,5.21) 21.25,4.85 23.77,4.85 24.26,5.33 28.7,5.33 29.27,4.76 32.58,4.76 33.78,3.56 37.47,3.56 40.77,6.86 44.83,6.86 46,8.03 50.89,8.03 v1(51.37,8.51)
  BOTTOM w0.254: v1(23.18,60.77) 22.29,60.77 22.16,60.64 R25.1
GPIO4_5: length 90.3
  TOP w0.152: J14.161 v1(84.02,10.92)
  INNER1 w0.152: v1(84.02,10.92) 84.02,6.85 85.53,5.33 85.53,4.44 85.28,4.19 69.22,4.19 65.66,7.75 63.12,7.75 62.48,7.11 62.48,6.67 61.98,6.16 54.04,6.16 51.82,3.94 v1(51.31,3.94)
  INNER2 w0.152: v1(51.31,3.94) 51.31,5.71 50.04,6.99 50.04,9.91 44.26,15.68 44.26,30.04 40.2,34.1 TP18.1
  BOTTOM w0.152: U6.9 33.9,32 34.73,32.83 34.73,33.4 TP18.1
GPIO4_6: length 88.1
  TOP w0.152: J14.163 v1(84.52,8.71)
  INNER1 w0.152: v1(84.52,8.71) 84.52,7.17 85.98,5.71 85.98,4.19 85.53,3.75 68.9,3.75 65.34,7.3 63.31,7.3 62.93,6.92 62.93,6.48 61.53,5.08 61.53,4.51 60.33,3.3 51.05,3.3 v1(50.42,3.94)
  INNER2 w0.152: TP19.1 36.2,33.53 40.01,33.53 43.81,29.72 43.81,15.37 49.15,10.03 49.15,6.99 50.42,5.71 v1(50.42,3.94)
  BOTTOM w0.152: U6.10 34.41,31.74 TP19.1
GPIO4_7: length 85.7
  TOP w0.152: J14.165 v1(85.02,10.92)
  INNER1 w0.152: v1(85.02,10.92) 85.02,7.88 87,5.91 87,4.51 85.79,3.3 65.53,3.3 64.61,2.38 61.25,2.38 60.83,2.79 50.67,2.79 v1(50.42,3.05)
  INNER2 w0.152: TP20.1 39.62,32.77 42.55,29.84 42.55,15.88 48.26,10.16 48.26,6.99 49.66,5.59 49.66,3.81 v1(50.42,3.05)
  BOTTOM w0.152: U6.14 36.41,31.07 37.27,31.94 37.27,32.32 TP20.1
GPIO4_8: length 83.8
  TOP w0.152: J14.167 v1(85.52,8.71)
  INNER1 w0.152: v1(49.53,3.05) 50.29,2.29 60.58,2.29 60.9,1.97 68.9,1.97 69.79,2.86 86.11,2.86 86.8,3.56 88.27,3.56 89.15,4.45 89.15,5.84 86.28,8.71 v1(85.52,8.71)
  INNER2 w0.152: v1(49.53,3.05) 49.02,3.56 49.02,5.46 47.24,7.24 47.24,9.14 41.91,14.48 41.91,27.69 38.23,31.37 TP21.1
  BOTTOM w0.152: TP21.1 36.9,30.55 U6.15
GPIO4_21: length 65.3
  TOP w0.152: U44.55 62.98,42.43 v1(64.39,41.02) ; v1(48.01,4.83) J14.58
  INNER1 w0.152: v1(48.01,4.83) 47.44,4.25 40.2,4.25 39.18,5.27 39.18,10.86 38.93,11.11 38.93,13.78 38.67,14.03 38.67,15.84 49.53,26.7 49.53,31.5 55.12,37.08 58.17,37.08 61.52,40.44 63.8,40.44 v1(64.39,41.02)
  BOTTOM w0.152: v1(64.39,41.02) 64.39,40.01 R287.1
GPIO4_22: length 22.6
  TOP w0.152: J14.60 48.51,2.79 v1(48.51,2.29) ; U22.1 v1(29.21,2.77)
  BOTTOM w0.152: v1(48.51,2.29) 42.16,2.29 41.91,2.54 33.27,2.54 32.38,3.43 R197.2 31.18,3.43 30.52,2.77 v1(29.21,2.77)
GPMC_AD3: length 69.6
  TOP w0.127: v1(79.52,1.97) J14.144 ; SW2.2 v1(15.24,3.17)
  INNER1 w0.127: v1(79.52,1.97) 79.01,2.48 70.17,2.48 69.22,1.52 60.33,1.52 60.2,1.65 42.8,1.65 41.97,2.48 31.43,2.48 30.61,1.65 28.7,1.65 28.07,2.29 25.91,2.29 25.08,1.46 16.95,1.46 v1(15.24,3.17)
GPMC_AD4: length 79.6
  TOP w0.127: J14.145 80.02,8.26 79.76,8 79.06,8 78.93,8.13 v1(74.93,8.13) ; SW2.1 v1(15.24,1.91)
  INNER1 w0.127: v1(78.61,1.97) 77.72,1.08 16.07,1.08 v1(15.24,1.91)
  INNER2 w0.127: v1(74.93,8.13) 75.63,7.43 75.63,4.95 v1(78.61,1.97)
GPMC_AD10: length 1.7
  TOP w0.127: R202.2 81.33,11.25 81.33,10.92 81.52,10.73 J14.151
GPMC_AD11: length 2.5
  TOP w0.127: J14.152 81.52,5.09 v1(81.41,5.21)
  BOTTOM w0.127: v1(81.41,5.21) 80.9,5.21 R201.1
GPMC_AD12: length 1.7
  TOP w0.127: R200.2 82.25,11.25 82.25,10.93 82.02,10.71 J14.153
GPMC_CS1: length 3.4
  TOP w0.127: TP58.1 74.68,12.13 74.68,11.11 75.02,10.77 J14.125
GPMC_CS2: length 1.7
  TOP w0.127: TP61.1 75.37,10.99 75.52,10.84 J14.127
GPMC_CS3: length 3.5
  TOP w0.127: J14.133 77.02,10.66 77.47,11.11 77.47,12.13 TP63.1
GPMC_CS4: length 1.7
  TOP w0.127: TP60.1 76.77,11.24 76.52,10.99 J14.131
GPMC_CS5: length 3.3
  TOP w0.127: J14.129 76.02,10.87 76.07,10.92 76.07,12.13 TP62.1
GPMC_CS6: length 1.8
  TOP w0.127: TP59.1 73.98,11.24 74.52,10.7 J14.123
HDMI_IN_5V0: length 3.3
  TOP w0.229: J26.18 v1(60.15,63.75)
  TOP w0.381: R275.1 v1(62.42,61.37)
  BOTTOM w0.381: R285.2 v1(64.52,46.61) ; v1(60.15,63.75) 59.69,63.3 C220.1
HDMI_IN_CEC: length 13.9
  TOP w0.127: v1(59.56,51.31) 59,51.87 U43.16 ; U44.61 62.45,45.43 64.52,47.5 64.51,47.5 R283.2 64.51,49.91 v1(63.63,50.8)
  BOTTOM w0.127: v1(63.63,50.8) 61.34,50.8 60.83,51.31 v1(59.56,51.31)
HDMI_IN_CLK: length 2.7
  TOP w0.127: R271.2 48.26,42.8 48.77,42.8 48.9,42.93 U44.25
HDMI_IN_CLKN: length 14.7
  TOP w0.127: J26.12 57.73,62.82 57.73,61.65 58.18,61.2 58.18,59.88 58.5,59.56 U43.24 58.5,57.5 58.18,57.17 58.18,54.33 58.5,54.01 U43.15 58.5,51.95 58.18,51.63 58.18,50.93 58.18,50.93 58.18,48.95 U44.3
HDMI_IN_CLKP: length 14.7
  TOP w0.127: J26.11 57.37,62.82 57.37,61.51 57.82,61.06 57.82,59.88 57.5,59.56 U43.26 57.5,57.5 57.82,57.17 57.82,54.33 57.5,54.01 U43.13 57.5,51.95 57.82,51.63 57.82,51.45 57.82,48.95 U44.4
HDMI_IN_D0: length 2.5
  TOP w0.127: U44.43 56.75,35.48 56.68,35.41 RN1.5
HDMI_IN_D0N: length 14.7
  TOP w0.127: J26.9 56.53,62.82 56.53,61.38 56.82,61.08 56.82,60.33 56.68,60.18 56.68,59.83 57,59.51 U43.27 57,57.5 56.68,57.17 56.68,54.33 57,54.01 U43.12 57,51.95 56.68,51.63 56.68,50.93 56.68,50.93 56.68,48.95 U44.6
HDMI_IN_D0P: length 14.7
  TOP w0.127: U44.7 56.32,48.95 56.32,51.45 56.32,51.45 56.32,51.63 56,51.95 U43.10 56,54.01 56.32,54.33 56.32,57.17 56,57.5 U43.29 56,59.51 56.32,59.83 56.32,60.33 56.47,60.48 56.47,60.93 56.17,61.23 56.17,62.82 J26.8
HDMI_IN_D1: length 2.5
  TOP w0.127: RN1.6 56.13,35.56 56.25,35.68 U44.42
HDMI_IN_D1N: length 14.7
  TOP w0.127: J26.6 55.33,62.82 55.33,61.37 55.03,61.07 55.03,60.46 55.18,60.31 55.18,59.83 55.5,59.51 U43.30 55.5,57.5 55.18,57.17 55.18,54.33 55.5,54.01 U43.9 55.5,51.95 55.18,51.63 55.18,50.93 55.18,50.93 55.18,48.95 U44.9
HDMI_IN_D1P: length 14.7
  TOP w0.127: J26.5 54.97,62.82 54.97,61.52 54.68,61.22 54.68,60.31 54.82,60.17 54.82,59.83 54.5,59.51 U43.32 54.5,57.5 54.82,57.17 54.82,54.33 54.5,54.01 U43.7 54.5,51.95 54.82,51.63 54.82,51.45 54.82,48.95 U44.10
HDMI_IN_D2: length 2.5
  TOP w0.127: U44.41 55.75,35.82 55.63,35.7 RN1.7
HDMI_IN_D2N: length 14.7
  TOP w0.127: J26.3 54.13,62.82 54.13,61.87 53.68,61.42 53.68,59.88 54,59.56 U43.33 54,57.5 53.68,57.17 53.68,54.33 54,54.01 U43.6 54,51.95 53.68,51.63 53.68,50.93 53.68,50.93 53.68,48.95 U44.12
HDMI_IN_D2P: length 14.7
  TOP w0.127: U44.13 53.32,48.95 53.32,51.45 53.32,51.45 53.32,51.63 53,51.95 U43.4 53,54.01 53.32,54.33 53.32,57.17 53,57.5 U43.35 53,59.56 53.32,59.88 53.32,61.57 53.77,62.02 53.77,62.82 J26.2
HDMI_IN_D3: length 2.6
  TOP w0.127: U44.39 54.75,35.8 55.08,35.47 RN1.8
HDMI_IN_D4: length 2.5
  TOP w0.127: RN2.5 54.14,35.53 54.25,35.64 U44.38
HDMI_IN_D5: length 2.5
  TOP w0.127: RN2.6 53.59,35.62 53.75,35.78 U44.37
HDMI_IN_D6: length 2.5
  TOP w0.127: U44.36 53.25,35.91 53.09,35.75 RN2.7
HDMI_IN_D7: length 2.5
  TOP w0.127: RN2.8 52.54,35.84 52.75,36.05 U44.35
HDMI_IN_D8: length 4.4
  TOP w0.127: RN3.5 47.88,38.32 50.48,37.91 U44.33
HDMI_IN_D9: length 2.6
  TOP w0.127: U44.32 48.7,39.43 48.14,38.87 RN3.6
HDMI_IN_D10: length 2.6
  TOP w0.127: RN3.7 48.03,39.37 48.59,39.93 U44.31
HDMI_IN_D11: length 2.5
  TOP w0.127: RN3.8 47.94,39.92 48.46,40.43 U44.30
HDMI_IN_D12: length 2.4
  TOP w0.127: RN4.5 48.22,40.86 48.3,40.93 U44.29
HDMI_IN_D13: length 2.3
  TOP w0.127: RN4.6 47.49,41.43 U44.28
HDMI_IN_D14: length 2.3
  TOP w0.127: RN4.7 47.49,41.93 U44.27
HDMI_IN_D15: length 2.3
  TOP w0.127: U44.26 47.49,42.43 RN4.8
HDMI_IN_DDC_SCL: length 18.3
  TOP w0.127: U43.17 v1(59.5,53.94) ; v1(63.63,48.77) 63.63,47.31 62.25,45.93 U44.62
  BOTTOM w0.127: v1(59.5,53.94) 60.71,52.73 U46.2 66.01,52.73 66.29,52.45 66.29,51.18 64.51,49.4 R281.2 v1(63.63,48.77)
HDMI_IN_DDC_SDA: length 16.2
  TOP w0.127: U44.63 62.11,46.43 62.99,47.31 62.99,51.31 63.44,51.75 v1(63.44,54.04) 60.26,54.04 60,53.78 U43.18
  BOTTOM w0.127: R282.2 62.68,54.04 v1(63.44,54.04) 64.08,54.68 U46.5
HDMI_IN_DE: length 2.4
  TOP w0.127: R274.2 57.75,35.09 U44.45
HDMI_IN_HPDET: length 5.7
  TOP w0.152: U44.1 59.25,49.79 60.5,51.04 U43.19 61.69,52.85 R286.1
HDMI_IN_HS: length 2.7
  TOP w0.127: U44.46 58.25,36.24 58.93,35.56 R272.2
HDMI_IN_VS: length 3.2
  TOP w0.127: R273.2 60.07,35.56 59.56,36.07 59.25,36.07 58.75,36.56 U44.47
HDMI_OUT_HPD: length 163.8
  TOP w0.127: U20.19 v1(108.71,49.66) ; v1(21.46,15.49) 24.38,12.57 24.38,6.73 23.68,6.02 U22.19
  INNER2 w0.127: v1(108.71,49.66) 108.72,49.66 109.35,50.29 109.35,61.98 102.74,68.58 97.66,68.58 96.27,67.18 96.27,64.52 93.98,62.23 88.52,62.23 84.58,66.17 73.41,66.17 73.15,66.42 67.54,66.42 63.35,62.23 44.96,62.23 43.81,63.37 39.12,63.37 35.94,60.2 35.94,57.15 27.43,48.64 27.43,21.59 21.46,15.62 v1(21.46,15.49)
  BOTTOM w0.127: R316.2 108.97,49.02 108.71,49.28 v1(108.71,49.66)
HDMI_OUT_SCL: length 89.3
  TOP w0.127: U20.17 v1(108.71,50.66) ; R320.2 R319.2 v1(48.39,59.56)
  INNER2 w0.127: v1(48.39,59.56) 48.9,59.05 61.98,59.05 68.83,65.91 72.9,65.91 73.15,65.66 84.33,65.66 88.27,61.72 94.23,61.72 96.77,64.26 96.77,66.93 97.92,68.07 102.49,68.07 107.82,62.74 107.82,51.55 v1(108.71,50.66)
  BOTTOM w0.127: v1(108.71,50.66) 108.71,51.05 108.97,51.31 R318.2
HDMI_OUT_SDA: length 88.8
  TOP w0.127: U20.18 v1(107.95,50.16)
  INNER2 w0.127: v1(48.26,58.04) 48.64,58.42 62.77,58.42 69.76,65.41 72.64,65.41 72.9,65.15 84.07,65.15 88.01,61.21 94.49,61.21 97.28,64.01 97.28,66.17 97.92,66.8 103,66.8 106.05,63.75 106.05,52.07 v1(107.95,50.16)
  BOTTOM w0.127: R317.2 107.95,50.16 v1(107.95,50.16) ; R321.2 R322.2 v1(48.26,58.04)
I2C1_SCL: length 107
  TOP w0.127: R291.1 v1(40.51,36.39) ; J14.156 v1(82.52,5.46) ; R319.1 J27.7
  INNER1 w0.127: v1(40.51,36.39) 42.23,38.1 42.23,38.54 44.45,40.77 44.45,47.75 44.7,48.01 44.7,57.28 J27.7
  INNER2 w0.127: v1(37.21,36.39) v1(40.51,36.39)
  BOTTOM w0.127: R38.2 v1(40.51,36.39) 43.62,33.27 44.7,33.27 47.12,30.86 59.94,30.86 60.33,31.24 66.93,31.24 69.22,28.96 69.22,9.27 68.58,8.64 68.58,5.97 69.98,4.57 72.77,4.57 73.91,5.71 75.31,5.71 75.76,5.27 78.61,5.27 79.31,4.57 81.63,4.57 v1(82.52,5.46) ; R43.2 v1(37.21,36.39)
I2C1_SDA: length 104.3
  TOP w0.127: v1(81.79,5.97) 82.02,5.74 J14.154 ; R292.1 v1(40.51,37.53)
  INNER1 w0.127: J27.9 44.2,55.24 44.2,48.26 43.94,48.01 43.94,40.96 v1(40.51,37.53)
  INNER2 w0.127: v1(37.21,37.53) v1(40.51,37.53)
  BOTTOM w0.127: v1(81.79,5.97) 82.23,6.41 82.23,6.92 81.79,7.37 79.38,7.37 78.61,6.6 75.95,6.6 75.5,6.16 73.72,6.16 72.64,5.08 70.17,5.08 69.09,6.16 69.09,8.38 69.66,8.95 69.66,29.27 67.18,31.75 60.07,31.75 59.69,31.37 47.37,31.37 44.83,33.91 44.13,33.91 v1(40.51,37.53) R36.2 ; R40.2 v1(37.21,37.53) ; R321.1 42.42,57.02 J27.9
I2C2_SCL: length 144.2
  TOP w0.127: R320.1 44.96,57.02 J27.11 ; R288.2 v1(40.51,35.24) ; J14.120 v1(68.52,2.48) ; v1(25.27,4.07) U22.22
  INNER1 w0.127: v1(37.21,35.24) 37.21,33.4 32.26,28.45 32.26,24.89 29.88,22.51 27.08,22.51 22.61,18.03 22.61,10.54 25.27,7.87 v1(25.27,4.07) ; J27.11 41.15,53.21 41.15,40.62 v1(40.92,40.39) 39.88,39.35 39.88,35.88 v1(40.51,35.24)
  INNER2 w0.127: v1(25.27,4.07) 28.95,4.07 29.84,3.17 48.51,3.17 49.66,2.03 63.63,2.03 64.39,1.27 67.31,1.27 v1(68.52,2.48) ; v1(37.21,35.24) v1(40.51,35.24)
  BOTTOM w0.127: U28.1 v1(40.92,40.39) ; U46.3 61.17,53.38 59.44,55.12 45.34,55.12 44.7,54.48 J27.11 ; R39.2 v1(40.51,35.24) ; R44.2 v1(37.21,35.24)
I2C2_SDA: length 148
  TOP w0.127: U22.23 v1(24.51,3.42) ; J14.122 72.67,3.65 v1(71.08,2.06) ; R289.2 v1(40.51,38.67)
  INNER1 w0.127: v1(37.21,38.67) 33.91,35.37 33.91,32 28.7,26.8 27.94,26.8 25.15,24 25.15,21.21 22.16,18.22 22.16,10.35 24.51,8 v1(24.51,3.42) ; J27.13 43.69,50.67 43.69,48.51 42.4,47.22 v1(42.4,40.39) v1(40.51,38.67)
  INNER2 w0.127: v1(71.08,2.06) 69.91,0.89 64.14,0.89 63.5,1.52 48.39,1.52 47.37,2.54 29.84,2.54 29.59,2.29 25.65,2.29 v1(24.51,3.42) ; v1(37.21,38.67) v1(40.51,38.67)
  BOTTOM w0.127: R37.2 v1(40.51,38.67) ; J27.13 41.15,53.21 41.15,55.24 41.59,55.69 45.59,55.69 46.1,56.2 R322.1 47.75,57.02 49.09,55.69 63.75,55.69 64.11,55.33 U46.6 ; R41.2 v1(37.21,38.67) ; U28.6 v1(42.4,40.39)
LPTX_C_N: length 6.6
  BOTTOM w0.127: TP6.1 24.45,34.59 24.32,34.72 23.93,34.72 23.75,34.54 23.75,33.44 23.82,33.37 23.93,33.37 24,33.29 24,33.19 23.93,33.11 23.82,33.11 23.75,33.04 23.75,32.64 24.23,32.16 24.23,31.52 R46.2 24.23,30.86 24.23,30.51 C62.2
LPTX_C_P: length 6.6
  BOTTOM w0.127: TP5.1 24.03,35.08 23.78,35.08 23.39,34.69 23.39,32.49 23.88,32.01 23.88,31.52 R46.1 23.88,30.86 23.88,30.51 C61.2
LPTXN: length 7.7
  BOTTOM w0.127: C62.1 24.23,28.73 24.23,28.35 24.47,28.11 24.57,28.11 24.63,28.17 24.74,28.17 24.81,28.1 24.81,27.99 24.75,27.93 24.75,27.83 24.83,27.75 24.93,27.75 24.99,27.81 25.1,27.81 25.17,27.74 25.17,27.63 25.11,27.57 25.11,27.47 25.4,27.18 26.31,27.18 27.97,25.53 29.13,25.53 U6.57
LPTXP: length 7.7
  BOTTOM w0.127: C61.1 23.88,28.73 23.88,28.2 25.25,26.82 26.17,26.82 27.82,25.17 29.13,25.17 U6.56
MDIO_D: length 50.4
  TOP w0.127: U9.17 91.56,38.24 R311.2 R125.2 91.44,40.38 TP47.1 90.3,41.02 88.65,39.37 84.71,39.37 80.77,35.43 80.77,31.37 61.52,12.11 J14.91
MDIO_MCLK: length 65
  TOP w0.127: U9.16 92.05,37.7 92.2,37.85 TP48.1 ; v1(72.39,5.78) 72.39,5.33 68.96,1.91 62.36,1.91 61.52,2.75 J14.92
  INNER1 w0.127: v1(72.39,5.78) 73.15,6.54 73.15,17.02 78.74,22.61 78.74,33.27 84.84,39.37 88.65,39.37 89.53,40.26 91.44,40.26 TP48.1
MMC_CLK: length 21.1
  TOP w0.127: J21.5 v1(81.79,69.09)
  INNER1 w0.127: v1(81.79,69.09) 81.79,68.07 81.67,67.94 81.15,67.94 81.03,67.81 81.03,67.56 81.15,67.43 81.67,67.43 81.79,67.3 81.79,67.05 81.67,66.92 81.15,66.92 81.03,66.8 81.03,66.54 81.15,66.42 81.67,66.42 81.79,66.29 81.79,66.03 81.67,65.91 81.15,65.91 81.03,65.78 81.03,65.53 81.15,65.4 81.67,65.4 81.79,65.27 81.79,65.02 81.67,64.89 81.15,64.89 81.03,64.76 81.03,64.51 81.15,64.38 81.67,64.38 81.79,64.26 81.79,64 81.67,63.88 81.22,63.88 81.09,63.75 81.09,63.49 81.22,63.37 81.67,63.37 81.79,63.24 81.79,62.55 v1(77.72,58.48)
  BOTTOM w0.127: R148.2 R155.2 v1(77.72,58.48)
MMC_CMD: length 21.2
  TOP w0.127: J21.3 v1(79.59,69.09)
  INNER1 w0.127: v1(75.44,64.45) 75.44,63.88 75.69,63.63 76.2,63.63 76.33,63.75 76.33,64.39 76.45,64.52 76.71,64.52 76.83,64.39 76.83,63.75 76.96,63.63 77.22,63.63 77.34,63.75 77.34,64.39 77.47,64.52 77.72,64.52 77.85,64.39 77.85,63.75 77.98,63.63 78.23,63.63 78.36,63.75 78.36,64.39 78.49,64.52 78.74,64.52 78.87,64.39 78.87,63.75 78.99,63.63 79.25,63.63 79.59,63.97 79.59,64.74 79.72,64.87 80.26,64.87 80.39,65 80.39,65.25 80.26,65.38 79.72,65.38 79.59,65.5 79.59,65.76 79.72,65.89 80.26,65.89 80.39,66.01 80.39,66.27 80.26,66.39 79.72,66.39 79.59,66.52 79.59,66.77 79.72,66.9 80.26,66.9 80.39,67.03 80.39,67.28 80.26,67.41 79.72,67.41 79.59,67.54 v1(79.59,69.09)
  BOTTOM w0.127: R154.2 R147.2 v1(75.44,64.45)
MMC_DAT0: length 21.1
  TOP w0.127: J21.7 v1(83.99,69.09)
  INNER1 w0.127: v1(80.01,58.48) 84.39,62.87 84.39,63.24 84.26,63.37 83.99,63.37 83.87,63.5 83.87,63.75 83.99,63.88 84.45,63.88 84.58,64 84.58,64.26 84.45,64.38 83.99,64.38 83.87,64.51 83.87,64.77 83.99,64.89 84.45,64.89 84.58,65.02 84.58,65.27 84.45,65.4 83.99,65.4 83.87,65.53 83.87,65.78 83.99,65.91 84.45,65.91 84.58,66.04 84.58,66.29 84.45,66.42 83.99,66.42 83.87,66.54 83.87,66.8 83.99,66.92 84.45,66.92 84.58,67.05 84.58,67.31 84.45,67.43 83.99,67.43 83.87,67.56 83.87,67.81 83.99,67.94 84.45,67.94 84.58,68.07 84.58,68.32 84.45,68.45 84.12,68.45 83.99,68.58 v1(83.99,69.09)
  BOTTOM w0.127: R149.2 R156.2 v1(80.01,58.48)
MMC_DAT1: length 21.1
  TOP w0.127: J21.8 v1(85.09,69.09)
  INNER1 w0.127: v1(85.09,69.09) 85.09,62.68 80.2,57.78 76.14,57.78 v1(75.44,58.48)
  BOTTOM w0.127: R150.2 R157.2 v1(75.44,58.48)
MMC_DAT2: length 21
  TOP w0.127: J21.1 v1(77.39,69.09)
  INNER1 w0.127: v1(72.01,64.77) 72.9,65.66 73.59,65.66 73.72,65.79 73.72,67.12 73.85,67.25 74.1,67.25 74.23,67.12 74.23,65.79 74.36,65.66 74.61,65.66 74.74,65.79 74.74,67.12 74.86,67.25 75.12,67.25 75.24,67.12 75.24,65.79 75.37,65.66 75.63,65.66 75.75,65.79 75.75,66.04 75.88,66.17 76.13,66.17 76.26,66.04 76.26,65.79 76.39,65.66 77.09,65.66 77.39,65.96 77.39,66.3 77.27,66.43 76.96,66.43 76.83,66.56 76.83,66.81 76.96,66.94 77.27,66.94 77.39,67.07 77.39,67.32 77.27,67.45 76.96,67.45 76.83,67.57 76.83,67.83 76.96,67.96 77.27,67.96 77.39,68.08 v1(77.39,69.09)
  BOTTOM w0.127: R152.2 R145.2 70.87,64.26 71.37,64.77 v1(72.01,64.77)
MMC_DAT3: length 21.1
  TOP w0.127: J21.2 v1(78.49,69.09)
  INNER1 w0.127: v1(78.49,69.09) 78.49,68.57 78.62,68.44 78.87,68.44 78.99,68.32 78.99,68.06 78.87,67.93 78.11,67.93 77.99,67.81 77.99,67.55 78.11,67.43 78.99,67.43 79.12,67.3 79.12,67.05 78.99,66.92 78.11,66.92 77.99,66.79 77.99,66.54 78.11,66.41 78.99,66.41 79.12,66.28 79.12,66.03 78.99,65.9 78.11,65.9 77.99,65.78 77.99,65.41 77.72,65.15 74.87,65.15 74.74,65.02 74.74,62.87 74.61,62.74 74.36,62.74 74.23,62.87 74.23,64.9 74.1,65.02 73.72,65.02 v1(73.15,64.45)
  BOTTOM w0.127: v1(73.15,64.45) R146.2 R153.2
NTRST: length 3.5
  TOP w0.152: v1(62.39,24.89) 62.63,25.13 R107.2 R110.1
  BOTTOM w0.152: J13.9 v1(62.39,24.89)
PB_RESETN: length 1.9
  TOP w0.152: TP77.1 86.52,10.66 J14.171
PG_1V1: length 9.5
  TOP w0.203: v1(95.27,3.96) 95.27,4.47 95.29,4.46
  TOP w0.254: U5.4 95.29,4.46
  BOTTOM w0.203: v1(95.27,3.96) 95.27,6.88 96.27,7.88 R34.1 96.27,10.67 TP69.1
PHY_LED0: length 3.1
  TOP w0.152: U9.47 93.05,26.86 D12.A
PHY_LED1: length 12
  TOP w0.152: v1(92.56,28.77) U9.46
  INNER2 w0.152: J24.15 97.79,27.43 94.74,27.43 94.23,26.92 92.46,26.92 91.69,27.69 91.69,28.32 92.14,28.77 v1(92.56,28.77)
PHY_LED2: length 15.9
  TOP w0.152: v1(92.33,27.88) 92.05,28.15 U9.45
  INNER2 w0.152: J24.14 98.43,35.18 97.28,35.18 95.89,33.78 95.89,29.34 93.98,27.43 92.77,27.43 v1(92.33,27.88)
PMIC_REGEN_3V3: length 2.6
  TOP w0.152: J14.26 40.01,2.79 40.96,1.84 TP80.1
PWRON: length 2
  TOP w0.152: J14.24 39.51,2.27 TP79.1
QSPI1_RTCLK: length 5.2
  TOP w0.127: TP57.1 73.28,13.53 73.28,10.29 73.75,9.82 J14.121
RGMII0_RXC: length 68.7
  TOP w0.127: J14.90 v1(61.02,4.85)
  INNER2 w0.127: v1(76.58,54.23) 76.58,44.64 62.87,30.92 62.87,29.97 59.23,26.34 59.23,25.91 59.74,25.4 59.74,24.33 60.83,23.24 60.83,21.36 61.02,21.18 61.02,19.28 60.89,19.16 59.94,19.16 59.82,19.03 59.82,18.78 59.94,18.65 60.89,18.65 61.02,18.52 61.02,18.27 60.89,18.14 59.94,18.14 59.82,18.01 59.82,17.76 59.94,17.63 60.89,17.63 61.02,17.51 61.02,16.71 61.14,16.58 61.47,16.58 61.59,16.45 61.59,16.2 61.47,16.07 61.14,16.07 61.02,15.94 61.02,15.69 61.14,15.56 61.47,15.56 61.59,15.44 61.59,15.18 61.47,15.05 61.14,15.05 61.02,14.93 61.02,14.67 61.14,14.55 61.47,14.55 61.59,14.42 61.59,14.17 61.47,14.04 61.14,14.04 61.02,13.91 61.02,13.66 61.14,13.53 61.47,13.53 61.59,13.4 61.59,13.15 61.47,13.02 61.14,13.02 61.02,12.9 v1(61.02,4.85)
  BOTTOM w0.127: R148.1 v1(76.58,54.23)
RGMII0_RXCTL: length 68.8
  TOP w0.127: J14.82 v1(59.02,4.85)
  INNER2 w0.127: v1(59.02,4.85) 59.02,15.15 56.13,18.03 56.13,22.42 56.45,22.73 56.45,23.11 56.13,23.43 56.13,27.3 60.52,31.69 60.9,31.69 73.53,44.32 73.53,59.18 v1(74.3,59.94)
  BOTTOM w0.127: R147.1 75.44,61.09 v1(74.3,59.94)
RGMII0_RXD0: length 68.7
  TOP w0.127: J14.86 v1(60.02,4.85)
  INNER2 w0.127: v1(60.02,4.85) 60.02,15.68 58.14,17.55 58.14,19.45 58.27,19.58 58.42,19.58 58.55,19.71 58.55,19.96 58.42,20.09 58.27,20.09 58.14,20.22 58.14,22.79 58.24,22.89 58.52,22.89 58.62,22.99 58.62,23.19 58.52,23.3 58.24,23.3 58.14,23.4 58.14,26.52 61.4,29.78 61.4,30.86 74.87,44.32 74.87,56.71 74.3,57.28 v1(74.3,58.8)
  BOTTOM w0.127: R146.1 73.15,59.94 v1(74.3,58.8)
RGMII0_RXD1: length 68.8
  TOP w0.127: J14.80 v1(58.52,5.59)
  INNER2 w0.127: v1(72.77,59.18) 72.77,44.2 60.71,32.13 60.33,32.13 55.13,26.94 55.13,18.28 58.52,14.89 v1(58.52,5.59)
  BOTTOM w0.127: R145.1 70.87,62.1 72.14,60.83 72.14,59.82 v1(72.77,59.18)
RGMII0_RXD2: length 68.7
  TOP w0.127: J14.84 v1(59.52,5.59)
  INNER2 w0.127: v1(74.3,56.07) 74.3,44.45 61.09,31.24 60.71,31.24 59.6,30.13 59.6,29.95 59.74,29.82 59.74,29.64 59.56,29.46 59.38,29.46 59.24,29.6 59.06,29.6 58.88,29.42 58.88,29.24 59.08,29.03 59.08,28.85 58.9,28.68 58.72,28.68 58.52,28.88 58.34,28.88 58.16,28.7 58.16,28.52 58.36,28.32 58.36,28.14 58.18,27.96 58,27.96 57.8,28.16 57.62,28.16 57.15,27.69 57.15,26.14 57.25,26.04 57.63,26.04 57.73,25.94 57.73,25.74 57.63,25.64 57.25,25.64 57.15,25.54 57.15,24.43 57.25,24.33 57.61,24.33 57.71,24.23 57.71,24.03 57.61,23.93 57.15,23.93 57.05,23.83 57.05,23.62 57.15,23.52 57.61,23.52 57.71,23.42 57.71,23.22 57.61,23.11 57.25,23.11 57.15,23.01 57.15,22.81 57.25,22.71 57.61,22.71 57.71,22.61 57.71,22.4 57.61,22.3 57.25,22.3 57.15,22.2 57.15,21.34 57.25,21.23 57.4,21.23 57.51,21.13 57.51,20.93 57.4,20.83 57.25,20.83 57.15,20.73 57.15,20.52 57.25,20.42 57.61,20.42 57.71,20.32 57.71,20.12 57.61,20.02 57.25,20.02 57.15,19.91 57.15,17.78 59.52,15.41 v1(59.52,5.59)
  BOTTOM w0.127: R150.1 v1(74.3,56.07)
RGMII0_RXD3: length 68.7
  TOP w0.127: J14.88 v1(60.52,5.59)
  INNER2 w0.127: v1(78.87,56.07) 77.41,56.07 75.82,54.48 75.82,44.58 62.48,31.24 62.48,30.23 58.72,26.47 58.72,25.78 59.23,25.27 59.23,23.76 59.33,23.66 59.52,23.66 59.63,23.55 59.63,23.35 59.52,23.25 59.35,23.25 59.25,23.15 59.25,22.9 59.35,22.8 59.72,22.8 59.82,22.69 59.82,22.49 59.72,22.39 59.33,22.39 59.23,22.29 59.23,21.08 59.33,20.98 60.3,20.98 60.4,20.88 60.4,20.68 60.3,20.57 59.33,20.57 59.23,20.47 59.23,20.27 59.33,20.17 60.3,20.17 60.4,20.07 60.4,19.86 60.3,19.76 59.33,19.76 59.23,19.66 59.23,17.22 60.52,15.94 v1(60.52,5.59)
  BOTTOM w0.127: R149.1 v1(78.87,56.07)
RGMII1_RXC: length 17.2
  TOP w0.127: v1(78.49,7.62) 80.24,7.62 80.37,7.75 80.37,7.94 80.5,8.06 80.75,8.06 80.88,7.94 80.88,7.75 81,7.62 81.31,7.62 82.52,8.83 J14.155 ; U48.2 v1(80.04,15.75)
  INNER1 w0.127: v1(78.49,7.62) 78.49,8.13 78.17,8.45 78.17,8.77 78.49,9.09 78.49,9.34 78.36,9.47 78.17,9.47 78.04,9.6 78.04,10.1 79.02,11.07 79.02,14.73 v1(80.04,15.75)
  BOTTOM w0.127: v1(80.04,15.75) 80.04,16.48 R199.1
